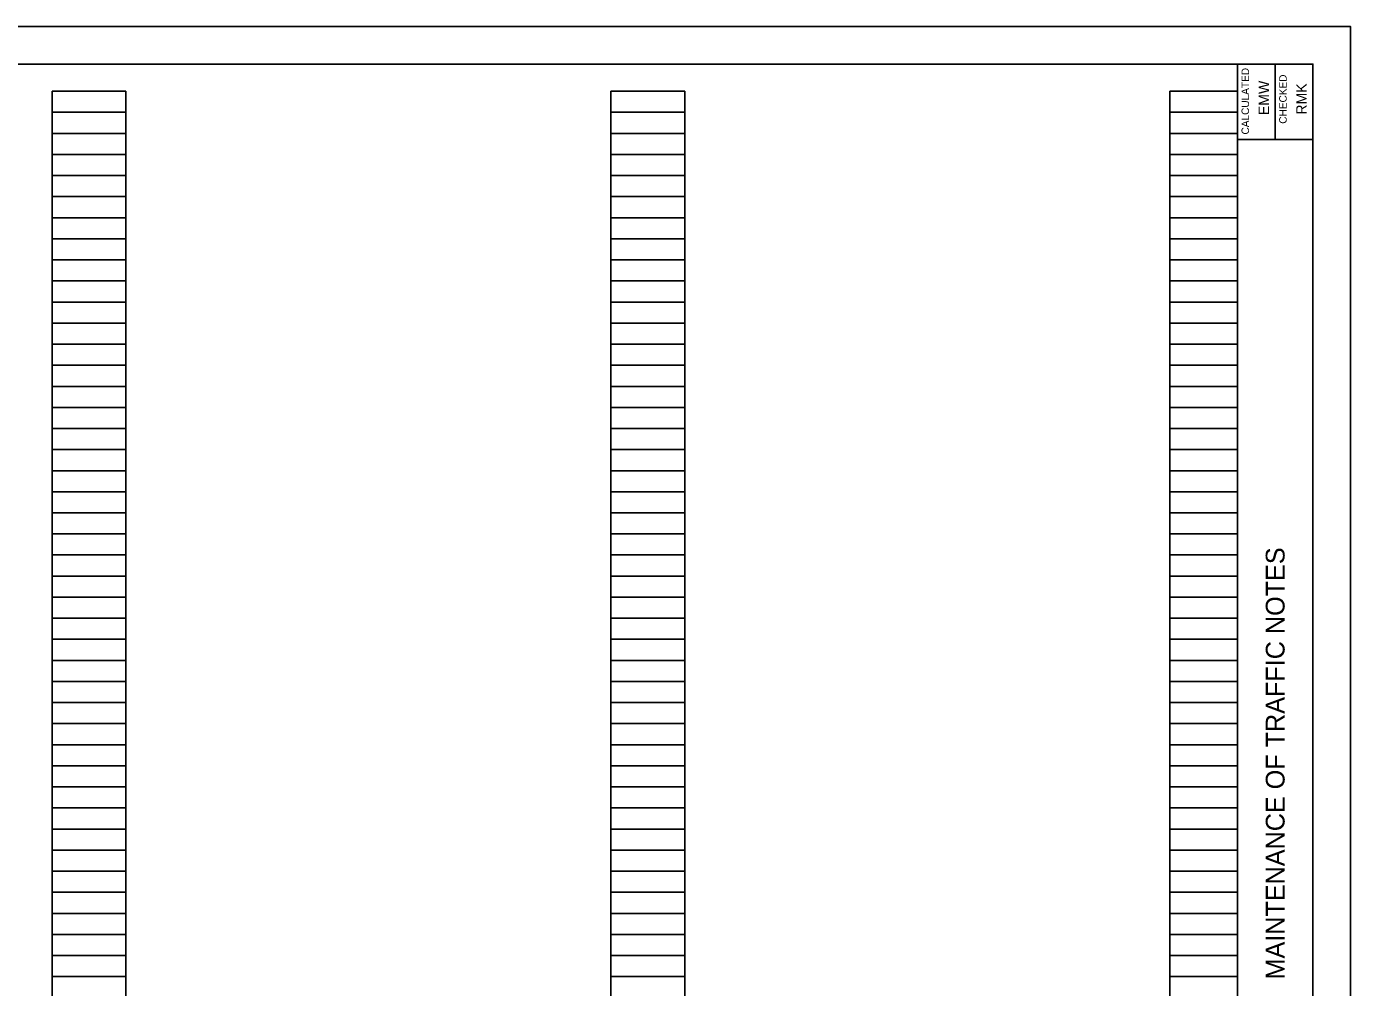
# Model space of a CAD drawing. Extents: x 1835969 to 1838545, y 714903 to 716193.
# Drawn here: x 1836019.22 to 1836036.8, y 714970.64 to 714983.41 of the extents above; entities that cross this region are included whole.
import ezdxf

# ---------------------------------------------------------------- set-up
doc = ezdxf.new("R2010")
doc.units = 0
for name, color, linetype in [('SC_Scratch2', 7, 'Continuous'), ('SH_Border', 7, 'Continuous'), ('SH_Cut_Line', 7, 'Continuous'), ('SH_Data', 7, 'Continuous')]:
    doc.layers.add(name, color=color, linetype=linetype)

msp = doc.modelspace()

# ---------------------------------------------------------------- linework, layer by layer
at = {"layer": 'SC_Scratch2'}
for p, q in [((1836019.561, 714962.39), (1836019.561, 714982.55)), ((1836019.561, 714982.55), (1836020.541, 714982.55)), ((1836020.541, 714962.39), (1836020.541, 714982.55)), ((1836026.981, 714962.39), (1836026.981, 714982.55)), ((1836026.981, 714982.55), (1836027.961, 714982.55)), ((1836027.961, 714962.39), (1836027.961, 714982.55)), ((1836034.401, 714962.39), (1836034.401, 714982.55)), ((1836034.401, 714982.55), (1836035.301, 714982.55)), ((1836035.301, 714962.39), (1836035.301, 714982.55)), ((1836019.561, 714982.27), (1836020.541, 714982.27)), ((1836026.981, 714982.27), (1836027.961, 714982.27)), ((1836034.401, 714982.27), (1836035.301, 714982.27)), ((1836019.561, 714981.99), (1836020.541, 714981.99)), ((1836026.981, 714981.99), (1836027.961, 714981.99)), ((1836034.401, 714981.99), (1836035.301, 714981.99)), ((1836019.561, 714981.71), (1836020.541, 714981.71)), ((1836026.981, 714981.71), (1836027.961, 714981.71)), ((1836034.401, 714981.71), (1836035.301, 714981.71)), ((1836019.561, 714981.43), (1836020.541, 714981.43)), ((1836026.981, 714981.43), (1836027.961, 714981.43)), ((1836034.401, 714981.43), (1836035.301, 714981.43)), ((1836019.561, 714981.15), (1836020.541, 714981.15)), ((1836026.981, 714981.15), (1836027.961, 714981.15)), ((1836034.401, 714981.15), (1836035.301, 714981.15)), ((1836019.561, 714980.87), (1836020.541, 714980.87)), ((1836026.981, 714980.87), (1836027.961, 714980.87)), ((1836034.401, 714980.87), (1836035.301, 714980.87)), ((1836019.561, 714980.59), (1836020.541, 714980.59)), ((1836026.981, 714980.59), (1836027.961, 714980.59)), ((1836034.401, 714980.59), (1836035.301, 714980.59)), ((1836019.561, 714980.31), (1836020.541, 714980.31)), ((1836026.981, 714980.31), (1836027.961, 714980.31)), ((1836034.401, 714980.31), (1836035.301, 714980.31)), ((1836019.561, 714980.03), (1836020.541, 714980.03)), ((1836026.981, 714980.03), (1836027.961, 714980.03)), ((1836034.401, 714980.03), (1836035.301, 714980.03)), ((1836019.561, 714979.75), (1836020.541, 714979.75)), ((1836026.981, 714979.75), (1836027.961, 714979.75)), ((1836034.401, 714979.75), (1836035.301, 714979.75)), ((1836019.561, 714979.47), (1836020.541, 714979.47)), ((1836026.981, 714979.47), (1836027.961, 714979.47)), ((1836034.401, 714979.47), (1836035.301, 714979.47)), ((1836019.561, 714979.19), (1836020.541, 714979.19)), ((1836026.981, 714979.19), (1836027.961, 714979.19)), ((1836034.401, 714979.19), (1836035.301, 714979.19)), ((1836019.561, 714978.91), (1836020.541, 714978.91)), ((1836026.981, 714978.91), (1836027.961, 714978.91)), ((1836034.401, 714978.91), (1836035.301, 714978.91)), ((1836019.561, 714978.63), (1836020.541, 714978.63)), ((1836026.981, 714978.63), (1836027.961, 714978.63)), ((1836034.401, 714978.63), (1836035.301, 714978.63)), ((1836019.561, 714978.35), (1836020.541, 714978.35)), ((1836026.981, 714978.35), (1836027.961, 714978.35)), ((1836034.401, 714978.35), (1836035.301, 714978.35)), ((1836019.561, 714978.07), (1836020.541, 714978.07)), ((1836026.981, 714978.07), (1836027.961, 714978.07)), ((1836034.401, 714978.07), (1836035.301, 714978.07)), ((1836019.561, 714977.79), (1836020.541, 714977.79)), ((1836026.981, 714977.79), (1836027.961, 714977.79)), ((1836034.401, 714977.79), (1836035.301, 714977.79)), ((1836019.561, 714977.51), (1836020.541, 714977.51)), ((1836026.981, 714977.51), (1836027.961, 714977.51)), ((1836034.401, 714977.51), (1836035.301, 714977.51)), ((1836019.561, 714977.23), (1836020.541, 714977.23)), ((1836026.981, 714977.23), (1836027.961, 714977.23)), ((1836034.401, 714977.23), (1836035.301, 714977.23)), ((1836019.561, 714976.95), (1836020.541, 714976.95)), ((1836026.981, 714976.95), (1836027.961, 714976.95)), ((1836034.401, 714976.95), (1836035.301, 714976.95)), ((1836019.561, 714976.67), (1836020.541, 714976.67)), ((1836026.981, 714976.67), (1836027.961, 714976.67)), ((1836034.401, 714976.67), (1836035.301, 714976.67)), ((1836019.561, 714976.39), (1836020.541, 714976.39)), ((1836026.981, 714976.39), (1836027.961, 714976.39)), ((1836034.401, 714976.39), (1836035.301, 714976.39)), ((1836019.561, 714976.11), (1836020.541, 714976.11)), ((1836026.981, 714976.11), (1836027.961, 714976.11)), ((1836034.401, 714976.11), (1836035.301, 714976.11)), ((1836019.561, 714975.83), (1836020.541, 714975.83)), ((1836026.981, 714975.83), (1836027.961, 714975.83)), ((1836034.401, 714975.83), (1836035.301, 714975.83)), ((1836019.561, 714975.55), (1836020.541, 714975.55)), ((1836026.981, 714975.55), (1836027.961, 714975.55)), ((1836034.401, 714975.55), (1836035.301, 714975.55)), ((1836019.561, 714975.27), (1836020.541, 714975.27)), ((1836026.981, 714975.27), (1836027.961, 714975.27)), ((1836034.401, 714975.27), (1836035.301, 714975.27)), ((1836019.561, 714974.99), (1836020.541, 714974.99)), ((1836026.981, 714974.99), (1836027.961, 714974.99)), ((1836034.401, 714974.99), (1836035.301, 714974.99)), ((1836019.561, 714974.71), (1836020.541, 714974.71)), ((1836026.981, 714974.71), (1836027.961, 714974.71)), ((1836034.401, 714974.71), (1836035.301, 714974.71)), ((1836019.561, 714974.43), (1836020.541, 714974.43)), ((1836026.981, 714974.43), (1836027.961, 714974.43)), ((1836034.401, 714974.43), (1836035.301, 714974.43)), ((1836019.561, 714974.15), (1836020.541, 714974.15)), ((1836026.981, 714974.15), (1836027.961, 714974.15)), ((1836034.401, 714974.15), (1836035.301, 714974.15)), ((1836019.561, 714973.87), (1836020.541, 714973.87)), ((1836026.981, 714973.87), (1836027.961, 714973.87)), ((1836034.401, 714973.87), (1836035.301, 714973.87)), ((1836019.561, 714973.59), (1836020.541, 714973.59)), ((1836026.981, 714973.59), (1836027.961, 714973.59)), ((1836034.401, 714973.59), (1836035.301, 714973.59)), ((1836019.561, 714973.31), (1836020.541, 714973.31)), ((1836026.981, 714973.31), (1836027.961, 714973.31)), ((1836034.401, 714973.31), (1836035.301, 714973.31)), ((1836019.561, 714973.03), (1836020.541, 714973.03)), ((1836026.981, 714973.03), (1836027.961, 714973.03)), ((1836034.401, 714973.03), (1836035.301, 714973.03)), ((1836019.561, 714972.75), (1836020.541, 714972.75)), ((1836026.981, 714972.75), (1836027.961, 714972.75)), ((1836034.401, 714972.75), (1836035.301, 714972.75)), ((1836019.561, 714972.47), (1836020.541, 714972.47)), ((1836026.981, 714972.47), (1836027.961, 714972.47)), ((1836034.401, 714972.47), (1836035.301, 714972.47)), ((1836019.561, 714972.19), (1836020.541, 714972.19)), ((1836026.981, 714972.19), (1836027.961, 714972.19)), ((1836034.401, 714972.19), (1836035.301, 714972.19)), ((1836019.561, 714971.91), (1836020.541, 714971.91)), ((1836026.981, 714971.91), (1836027.961, 714971.91)), ((1836034.401, 714971.91), (1836035.301, 714971.91)), ((1836019.561, 714971.63), (1836020.541, 714971.63)), ((1836026.981, 714971.63), (1836027.961, 714971.63)), ((1836034.401, 714971.63), (1836035.301, 714971.63)), ((1836019.561, 714971.35), (1836020.541, 714971.35)), ((1836026.981, 714971.35), (1836027.961, 714971.35)), ((1836034.401, 714971.35), (1836035.301, 714971.35)), ((1836019.561, 714971.07), (1836020.541, 714971.07)), ((1836026.981, 714971.07), (1836027.961, 714971.07)), ((1836034.401, 714971.07), (1836035.301, 714971.07)), ((1836019.561, 714970.79), (1836020.541, 714970.79)), ((1836026.981, 714970.79), (1836027.961, 714970.79)), ((1836034.401, 714970.79), (1836035.301, 714970.79))]:
    msp.add_line(p, q, dxfattribs=at)
at = {"layer": 'SH_Border'}
for p, q in [((1836035.301, 714961.91), (1836035.301, 714982.91)), ((1836035.801, 714982.91), (1836035.801, 714981.91)), ((1836035.301, 714981.91), (1836036.301, 714981.91))]:
    msp.add_line(p, q, dxfattribs=at)
msp.add_lwpolyline([(1836004.801, 714982.91), (1836036.301, 714982.91), (1836036.301, 714961.91), (1836004.801, 714961.91)], close=True, dxfattribs=at)
at = {"layer": 'SH_Cut_Line'}
msp.add_lwpolyline([(1836002.801, 714961.41), (1836036.801, 714961.41), (1836036.801, 714983.41), (1836002.801, 714983.41)], close=True, dxfattribs=at)
at = {"layer": 'SH_Data'}
for p, q in [((1836019.561, 714962.39), (1836019.561, 714982.55)), ((1836019.561, 714982.55), (1836020.541, 714982.55)), ((1836020.541, 714962.39), (1836020.541, 714982.55)), ((1836026.981, 714962.39), (1836026.981, 714982.55)), ((1836026.981, 714982.55), (1836027.961, 714982.55)), ((1836027.961, 714962.39), (1836027.961, 714982.55)), ((1836034.401, 714962.39), (1836034.401, 714982.55)), ((1836034.401, 714982.55), (1836035.301, 714982.55)), ((1836035.301, 714962.39), (1836035.301, 714982.55)), ((1836019.561, 714982.27), (1836020.541, 714982.27)), ((1836026.981, 714982.27), (1836027.961, 714982.27)), ((1836034.401, 714982.27), (1836035.301, 714982.27)), ((1836019.561, 714981.99), (1836020.541, 714981.99)), ((1836026.981, 714981.99), (1836027.961, 714981.99)), ((1836034.401, 714981.99), (1836035.301, 714981.99)), ((1836019.561, 714981.71), (1836020.541, 714981.71)), ((1836026.981, 714981.71), (1836027.961, 714981.71)), ((1836034.401, 714981.71), (1836035.301, 714981.71)), ((1836019.561, 714981.43), (1836020.541, 714981.43)), ((1836026.981, 714981.43), (1836027.961, 714981.43)), ((1836034.401, 714981.43), (1836035.301, 714981.43)), ((1836019.561, 714981.15), (1836020.541, 714981.15)), ((1836026.981, 714981.15), (1836027.961, 714981.15)), ((1836034.401, 714981.15), (1836035.301, 714981.15)), ((1836019.561, 714980.87), (1836020.541, 714980.87)), ((1836026.981, 714980.87), (1836027.961, 714980.87)), ((1836034.401, 714980.87), (1836035.301, 714980.87)), ((1836019.561, 714980.59), (1836020.541, 714980.59)), ((1836026.981, 714980.59), (1836027.961, 714980.59)), ((1836034.401, 714980.59), (1836035.301, 714980.59)), ((1836019.561, 714980.31), (1836020.541, 714980.31)), ((1836026.981, 714980.31), (1836027.961, 714980.31)), ((1836034.401, 714980.31), (1836035.301, 714980.31)), ((1836019.561, 714980.03), (1836020.541, 714980.03)), ((1836026.981, 714980.03), (1836027.961, 714980.03)), ((1836034.401, 714980.03), (1836035.301, 714980.03)), ((1836019.561, 714979.75), (1836020.541, 714979.75)), ((1836026.981, 714979.75), (1836027.961, 714979.75)), ((1836034.401, 714979.75), (1836035.301, 714979.75)), ((1836019.561, 714979.47), (1836020.541, 714979.47)), ((1836026.981, 714979.47), (1836027.961, 714979.47)), ((1836034.401, 714979.47), (1836035.301, 714979.47)), ((1836019.561, 714979.19), (1836020.541, 714979.19)), ((1836026.981, 714979.19), (1836027.961, 714979.19)), ((1836034.401, 714979.19), (1836035.301, 714979.19)), ((1836019.561, 714978.91), (1836020.541, 714978.91)), ((1836026.981, 714978.91), (1836027.961, 714978.91)), ((1836034.401, 714978.91), (1836035.301, 714978.91)), ((1836019.561, 714978.63), (1836020.541, 714978.63)), ((1836026.981, 714978.63), (1836027.961, 714978.63)), ((1836034.401, 714978.63), (1836035.301, 714978.63)), ((1836019.561, 714978.35), (1836020.541, 714978.35)), ((1836026.981, 714978.35), (1836027.961, 714978.35)), ((1836034.401, 714978.35), (1836035.301, 714978.35)), ((1836019.561, 714978.07), (1836020.541, 714978.07)), ((1836026.981, 714978.07), (1836027.961, 714978.07)), ((1836034.401, 714978.07), (1836035.301, 714978.07)), ((1836019.561, 714977.79), (1836020.541, 714977.79)), ((1836026.981, 714977.79), (1836027.961, 714977.79)), ((1836034.401, 714977.79), (1836035.301, 714977.79)), ((1836019.561, 714977.51), (1836020.541, 714977.51)), ((1836026.981, 714977.51), (1836027.961, 714977.51)), ((1836034.401, 714977.51), (1836035.301, 714977.51)), ((1836019.561, 714977.23), (1836020.541, 714977.23)), ((1836026.981, 714977.23), (1836027.961, 714977.23)), ((1836034.401, 714977.23), (1836035.301, 714977.23)), ((1836019.561, 714976.95), (1836020.541, 714976.95)), ((1836026.981, 714976.95), (1836027.961, 714976.95)), ((1836034.401, 714976.95), (1836035.301, 714976.95)), ((1836019.561, 714976.67), (1836020.541, 714976.67)), ((1836026.981, 714976.67), (1836027.961, 714976.67)), ((1836034.401, 714976.67), (1836035.301, 714976.67)), ((1836019.561, 714976.39), (1836020.541, 714976.39)), ((1836026.981, 714976.39), (1836027.961, 714976.39)), ((1836034.401, 714976.39), (1836035.301, 714976.39)), ((1836019.561, 714976.11), (1836020.541, 714976.11)), ((1836026.981, 714976.11), (1836027.961, 714976.11)), ((1836034.401, 714976.11), (1836035.301, 714976.11)), ((1836019.561, 714975.83), (1836020.541, 714975.83)), ((1836026.981, 714975.83), (1836027.961, 714975.83)), ((1836034.401, 714975.83), (1836035.301, 714975.83)), ((1836019.561, 714975.55), (1836020.541, 714975.55)), ((1836026.981, 714975.55), (1836027.961, 714975.55)), ((1836034.401, 714975.55), (1836035.301, 714975.55)), ((1836019.561, 714975.27), (1836020.541, 714975.27)), ((1836026.981, 714975.27), (1836027.961, 714975.27)), ((1836034.401, 714975.27), (1836035.301, 714975.27)), ((1836019.561, 714974.99), (1836020.541, 714974.99)), ((1836026.981, 714974.99), (1836027.961, 714974.99)), ((1836034.401, 714974.99), (1836035.301, 714974.99)), ((1836019.561, 714974.71), (1836020.541, 714974.71)), ((1836026.981, 714974.71), (1836027.961, 714974.71)), ((1836034.401, 714974.71), (1836035.301, 714974.71)), ((1836019.561, 714974.43), (1836020.541, 714974.43)), ((1836026.981, 714974.43), (1836027.961, 714974.43)), ((1836034.401, 714974.43), (1836035.301, 714974.43)), ((1836019.561, 714974.15), (1836020.541, 714974.15)), ((1836026.981, 714974.15), (1836027.961, 714974.15)), ((1836034.401, 714974.15), (1836035.301, 714974.15)), ((1836019.561, 714973.87), (1836020.541, 714973.87)), ((1836026.981, 714973.87), (1836027.961, 714973.87)), ((1836034.401, 714973.87), (1836035.301, 714973.87)), ((1836019.561, 714973.59), (1836020.541, 714973.59)), ((1836026.981, 714973.59), (1836027.961, 714973.59)), ((1836034.401, 714973.59), (1836035.301, 714973.59)), ((1836019.561, 714973.31), (1836020.541, 714973.31)), ((1836026.981, 714973.31), (1836027.961, 714973.31)), ((1836034.401, 714973.31), (1836035.301, 714973.31)), ((1836019.561, 714973.03), (1836020.541, 714973.03)), ((1836026.981, 714973.03), (1836027.961, 714973.03)), ((1836034.401, 714973.03), (1836035.301, 714973.03)), ((1836019.561, 714972.75), (1836020.541, 714972.75)), ((1836026.981, 714972.75), (1836027.961, 714972.75)), ((1836034.401, 714972.75), (1836035.301, 714972.75)), ((1836019.561, 714972.47), (1836020.541, 714972.47)), ((1836026.981, 714972.47), (1836027.961, 714972.47)), ((1836034.401, 714972.47), (1836035.301, 714972.47)), ((1836019.561, 714972.19), (1836020.541, 714972.19)), ((1836026.981, 714972.19), (1836027.961, 714972.19)), ((1836034.401, 714972.19), (1836035.301, 714972.19)), ((1836019.561, 714971.91), (1836020.541, 714971.91)), ((1836026.981, 714971.91), (1836027.961, 714971.91)), ((1836034.401, 714971.91), (1836035.301, 714971.91)), ((1836019.561, 714971.63), (1836020.541, 714971.63)), ((1836026.981, 714971.63), (1836027.961, 714971.63)), ((1836034.401, 714971.63), (1836035.301, 714971.63)), ((1836019.561, 714971.35), (1836020.541, 714971.35)), ((1836026.981, 714971.35), (1836027.961, 714971.35)), ((1836034.401, 714971.35), (1836035.301, 714971.35)), ((1836019.561, 714971.07), (1836020.541, 714971.07)), ((1836026.981, 714971.07), (1836027.961, 714971.07)), ((1836034.401, 714971.07), (1836035.301, 714971.07)), ((1836019.561, 714970.79), (1836020.541, 714970.79)), ((1836026.981, 714970.79), (1836027.961, 714970.79)), ((1836034.401, 714970.79), (1836035.301, 714970.79))]:
    msp.add_line(p, q, dxfattribs=at)

# ---------------------------------------------------------------- texts
for s, height, p in [('CALCULATED', 0.1, (1836035.454, 714981.975)), ('EMW', 0.14, (1836035.721, 714982.232)), ('CHECKED', 0.1, (1836035.954, 714982.118)), ('RMK', 0.14, (1836036.221, 714982.239)), ('MAINTENANCE OF TRAFFIC NOTES', 0.25, (1836035.926, 714970.752))]:
    msp.add_text(s, height=height, rotation=90, dxfattribs=at).set_placement(p)

doc.saveas('drawing.dxf')
